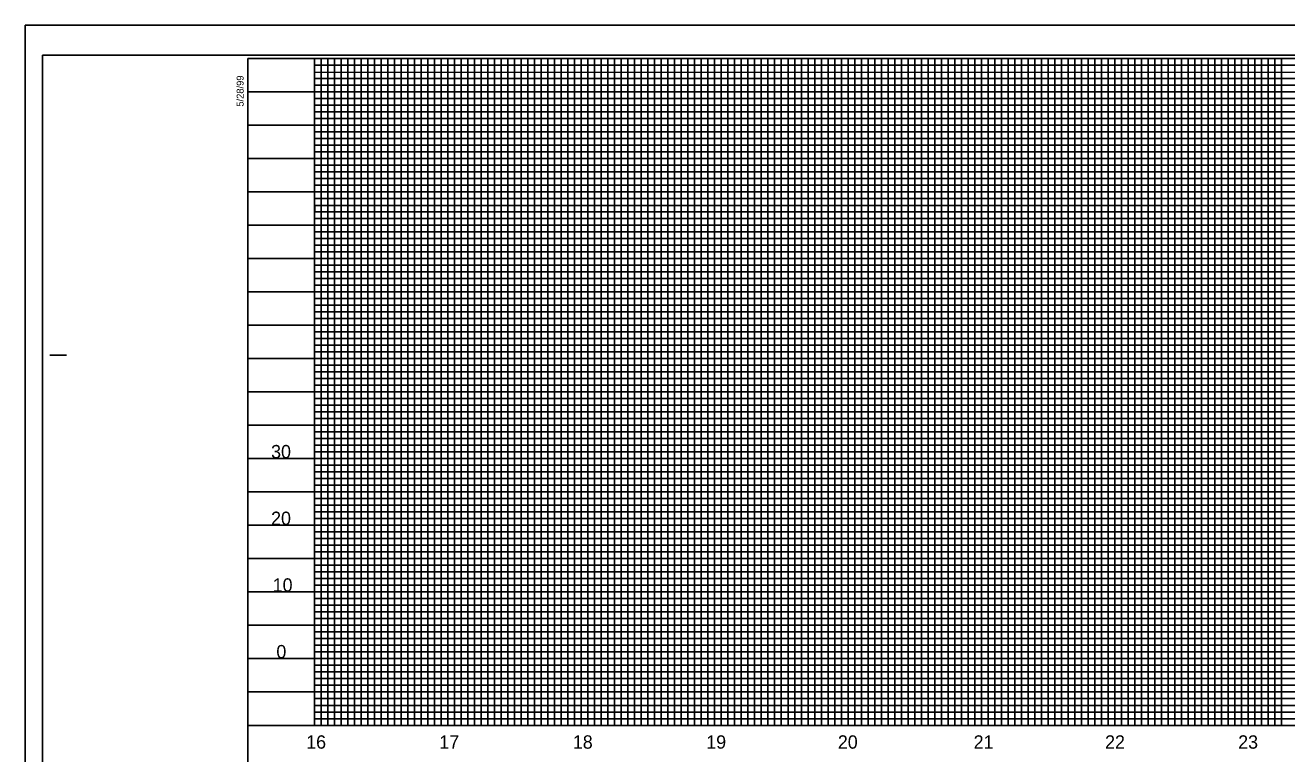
# Model space of a CAD drawing. Extents: x 2180324 to 2182216, y 74532 to 75632.
# Drawn here: x 2180324 to 2181270, y 75086 to 75632 of the extents above; entities that cross this region are included whole.
import ezdxf

# ---------------------------------------------------------------- set-up
doc = ezdxf.new("R2010")
doc.units = 0
for name, color, linetype in [('Old_Level_1', 7, 'Continuous'), ('Old_Level_11', 7, 'Continuous'), ('Old_Level_2', 7, 'Continuous'), ('Old_Level_3', 7, 'Continuous'), ('Scratch_Level_0', 7, 'Continuous'), ('Sheet Cutting Line CELL', 7, 'Continuous'), ('Sheet Plot Border Inside CELL', 7, 'Continuous'), ('Sheet Plot Border Outside CELL', 7, 'Continuous'), ('Sheet Sticker Exception Certification CELL', 7, 'Continuous'), ('Sheet Sticker Incomplete CELL', 7, 'Continuous'), ('Sheet Sticker Preliminary CELL', 7, 'Continuous')]:
    doc.layers.add(name, color=color, linetype=linetype)

msp = doc.modelspace()

# ---------------------------------------------------------------- linework, layer by layer
at = {"layer": 'Old_Level_11'}
for p, q in [((2180540.9, 75107.28), (2180540.9, 75607.28)), ((2180590.9, 75107.28), (2180590.9, 75607.28)), ((2180640.9, 75107.28), (2180640.9, 75607.28)), ((2180690.9, 75107.28), (2180690.9, 75607.28)), ((2180740.9, 75107.28), (2180740.9, 75607.28)), ((2180790.9, 75107.28), (2180790.9, 75607.28)), ((2180840.9, 75107.28), (2180840.9, 75607.28)), ((2180890.9, 75107.28), (2180890.9, 75607.28)), ((2180940.9, 75107.28), (2180940.9, 75607.28)), ((2180990.9, 75107.28), (2180990.9, 75607.28)), ((2181040.9, 75107.28), (2181040.9, 75607.28)), ((2181090.9, 75107.28), (2181090.9, 75607.28)), ((2181140.9, 75107.28), (2181140.9, 75607.28)), ((2181190.9, 75107.28), (2181190.9, 75607.28)), ((2181240.9, 75107.28), (2181240.9, 75607.28)), ((2181790.85, 75557.28), (2180490.9, 75557.28)), ((2181790.85, 75507.28), (2180490.9, 75507.28)), ((2181790.9, 75457.28), (2180490.9, 75457.28)), ((2181990.9, 75407.28), (2180490.9, 75407.28)), ((2181990.9, 75357.28), (2180490.9, 75357.28)), ((2181990.9, 75307.28), (2180490.9, 75307.28)), ((2181990.9, 75257.28), (2180490.9, 75257.28)), ((2181990.9, 75207.28), (2180490.9, 75207.28)), ((2181990.9, 75157.28), (2180490.9, 75157.28))]:
    msp.add_line(p, q, dxfattribs=at)
at = {"layer": 'Old_Level_2'}
msp.add_line((2180490.9, 75582.28), (2181790.85, 75582.28), dxfattribs=at)
for points in [[(2180565.9, 75607.28), (2180565.9, 75107.28), (2180615.9, 75107.28), (2180615.9, 75607.28), (2180665.9, 75607.28), (2180665.9, 75107.28), (2180715.9, 75107.28), (2180715.9, 75607.28), (2180765.9, 75607.28), (2180765.9, 75107.28), (2180815.9, 75107.28), (2180815.9, 75607.28), (2180865.9, 75607.28), (2180865.9, 75107.28), (2180915.9, 75107.28), (2180915.9, 75607.28), (2180965.9, 75607.28), (2180965.9, 75107.28), (2181015.9, 75107.28), (2181015.9, 75607.28), (2181065.9, 75607.28), (2181065.9, 75107.28), (2181115.9, 75107.28), (2181115.9, 75107.28), (2181115.9, 75607.28), (2181165.9, 75607.28), (2181165.9, 75107.28), (2181215.9, 75107.28), (2181215.9, 75607.28), (2181265.9, 75607.28), (2181265.9, 75107.28), (2181315.9, 75107.28)], [(2181790.9, 75532.28), (2180490.9, 75532.28), (2180490.9, 75482.28), (2181790.9, 75482.28)], [(2181990.9, 75432.28), (2180490.9, 75432.28), (2180490.9, 75382.28), (2181815.9, 75382.28)], [(2181990.9, 75332.28), (2180490.9, 75332.28), (2180490.9, 75282.28), (2181990.9, 75282.28)], [(2181990.9, 75232.28), (2180490.9, 75232.28), (2180490.9, 75182.28), (2181990.9, 75182.28)], [(2181990.9, 75132.28), (2180490.9, 75132.28)]]:
    msp.add_lwpolyline(points, dxfattribs=at)
at = {"layer": 'Scratch_Level_0'}
for p, q in [((2182007.9, 75632.28), (2180323.9, 75632.28)), ((2180323.9, 75632.28), (2180323.9, 74532.28))]:
    msp.add_line(p, q, dxfattribs=at)
at = {"layer": 'Sheet Cutting Line CELL'}
for p, q in [((2180342.4, 75384.78), (2180354.9, 75384.78)), ((2180490.9, 75107.28), (2181990.9, 75107.28))]:
    msp.add_line(p, q, dxfattribs=at)
msp.add_lwpolyline([(2181990.9, 75607.28), (2180490.9, 75607.28), (2180490.9, 74557.28), (2181990.9, 74557.28)], close=True, dxfattribs=at)
at = {"layer": 'Sheet Plot Border Inside CELL'}
msp.add_lwpolyline([(2180540.9, 75446.23), (2180540.9, 75107.28), (2181940.9, 75107.28), (2181940.9, 75446.23)], dxfattribs=at)
at = {"layer": 'Sheet Plot Border Outside CELL'}
for p, q in [((2180540.9, 75602.28), (2181790.9, 75602.28)), ((2180540.9, 75597.28), (2180540.9, 75597.28)), ((2181790.9, 75597.28), (2180540.9, 75596.93)), ((2180540.9, 75592.28), (2181790.9, 75592.28)), ((2181790.85, 75472.28), (2180540.9, 75472.28)), ((2181790.9, 75467.28), (2180540.9, 75467.28)), ((2181790.9, 75462.28), (2180540.9, 75462.28)), ((2180540.9, 75452.28), (2181790.9, 75452.28)), ((2181790.9, 75447.28), (2180540.9, 75447.28)), ((2180540.9, 75442.28), (2181940.9, 75442.28)), ((2181940.9, 75422.28), (2180540.9, 75422.28)), ((2180540.9, 75417.28), (2181940.9, 75417.28)), ((2181940.9, 75397.28), (2180540.9, 75397.28)), ((2180540.9, 75392.28), (2181940.9, 75392.28)), ((2181940.9, 75372.28), (2180540.9, 75372.28)), ((2180540.9, 75367.28), (2181940.9, 75367.28)), ((2181940.9, 75362.28), (2180540.9, 75362.28)), ((2180540.9, 75352.28), (2181940.9, 75352.28)), ((2181940.9, 75347.28), (2180540.9, 75347.28)), ((2180540.9, 75342.28), (2181940.9, 75342.28)), ((2181940.9, 75337.28), (2180540.9, 75337.28)), ((2180540.9, 75327.28), (2181940.9, 75327.28)), ((2181940.9, 75322.28), (2180540.9, 75322.28)), ((2180540.9, 75317.28), (2181940.9, 75317.28)), ((2181940.9, 75312.28), (2180540.9, 75312.28)), ((2180540.9, 75302.28), (2181940.9, 75302.28)), ((2181940.9, 75297.28), (2180540.9, 75297.28)), ((2180540.9, 75292.28), (2181940.9, 75292.28)), ((2181940.9, 75287.28), (2180540.9, 75287.28)), ((2180540.9, 75277.28), (2181940.9, 75277.28)), ((2181940.9, 75272.28), (2180540.9, 75272.28)), ((2180540.9, 75267.28), (2181940.9, 75267.28)), ((2181940.9, 75262.28), (2180540.9, 75262.28)), ((2180540.9, 75252.28), (2181940.9, 75252.28)), ((2181940.9, 75247.28), (2180540.9, 75247.28)), ((2180540.9, 75242.28), (2181940.9, 75242.28)), ((2181940.9, 75237.28), (2180540.9, 75237.28)), ((2180540.9, 75227.28), (2181940.9, 75227.28)), ((2181940.9, 75222.28), (2180540.9, 75222.28)), ((2181940.9, 75217.28), (2180540.9, 75217.28)), ((2181940.9, 75212.28), (2180540.9, 75212.28)), ((2180540.9, 75202.28), (2181940.9, 75202.28)), ((2181940.9, 75197.28), (2180540.9, 75197.28)), ((2180540.9, 75192.28), (2181940.9, 75192.28)), ((2181940.9, 75187.28), (2180540.9, 75187.28)), ((2180540.9, 75177.28), (2181940.9, 75177.28)), ((2181940.9, 75172.28), (2180540.9, 75172.28)), ((2180540.9, 75167.28), (2181940.9, 75167.28)), ((2181940.9, 75162.28), (2180540.9, 75162.28)), ((2180540.9, 75152.28), (2181940.9, 75152.28)), ((2181940.9, 75147.28), (2180540.9, 75147.28)), ((2180540.9, 75142.28), (2181940.9, 75142.28)), ((2181940.9, 75137.28), (2180540.9, 75137.28)), ((2180540.9, 75127.28), (2181940.9, 75127.28)), ((2181940.9, 75122.28), (2180540.9, 75122.28)), ((2180540.9, 75117.28), (2181940.9, 75117.28))]:
    msp.add_line(p, q, dxfattribs=at)
for points in [[(2180545.9, 75607.28), (2180545.9, 75107.28), (2180550.9, 75107.28), (2180550.9, 75607.28), (2180555.9, 75607.28), (2180555.9, 75107.28), (2180560.9, 75107.28), (2180560.9, 75607.28), (2180570.9, 75607.28), (2180570.9, 75107.28), (2180575.9, 75107.28), (2180575.9, 75607.28), (2180580.9, 75607.28), (2180580.9, 75107.28), (2180585.9, 75107.28), (2180595.9, 75107.28), (2180600.9, 75107.28), (2180600.9, 75607.28), (2180605.9, 75607.28), (2180605.9, 75107.28), (2180610.9, 75107.28), (2180610.9, 75607.28), (2180620.9, 75607.28), (2180620.9, 75107.28), (2180625.9, 75107.28), (2180625.9, 75607.28), (2180630.9, 75607.28), (2180630.9, 75107.28), (2180635.9, 75107.28), (2180635.9, 75607.28), (2180645.9, 75607.28), (2180645.9, 75107.28), (2180650.9, 75107.28), (2180650.9, 75607.28), (2180655.9, 75607.28), (2180655.9, 75107.28), (2180660.9, 75107.28), (2180660.9, 75607.28), (2180670.9, 75607.28), (2180670.9, 75107.28), (2180675.9, 75107.28), (2180675.9, 75607.28), (2180680.9, 75607.28), (2180680.9, 75107.28), (2180685.9, 75107.28), (2180685.9, 75607.28), (2180695.9, 75607.28), (2180695.9, 75107.28), (2180700.9, 75107.28), (2180700.9, 75607.28), (2180705.9, 75607.28), (2180705.9, 75107.28), (2180710.9, 75107.28), (2180710.9, 75607.28), (2180720.9, 75607.28), (2180720.9, 75107.28), (2180725.9, 75107.28), (2180725.9, 75607.28), (2180730.9, 75607.28), (2180730.9, 75107.28), (2180735.9, 75107.28), (2180735.9, 75607.28), (2180745.9, 75607.28), (2180745.9, 75107.28), (2180750.9, 75107.28), (2180750.9, 75607.28), (2180755.9, 75607.28), (2180755.9, 75107.28)], [(2180585.9, 75107.28), (2180585.9, 75607.28), (2180595.9, 75607.28), (2180595.9, 75107.28)], [(2180755.9, 75107.28), (2180760.9, 75107.28), (2180760.9, 75607.28), (2180770.9, 75607.28), (2180770.9, 75107.28), (2180775.9, 75107.28), (2180775.9, 75607.28), (2180780.9, 75607.28), (2180780.9, 75107.28), (2180785.9, 75107.28), (2180785.9, 75607.28), (2180795.9, 75607.28), (2180795.9, 75107.28), (2180800.9, 75107.28), (2180800.9, 75607.28), (2180805.9, 75607.28), (2180805.9, 75107.28), (2180810.9, 75107.28), (2180810.9, 75607.28), (2180820.9, 75607.28), (2180820.9, 75107.28), (2180825.9, 75107.28), (2180825.9, 75607.28), (2180830.9, 75607.28), (2180830.9, 75107.28), (2180835.9, 75107.28), (2180835.9, 75607.28), (2180845.9, 75607.28), (2180845.9, 75107.28), (2180850.9, 75107.28), (2180850.9, 75607.28), (2180855.9, 75607.28), (2180855.9, 75107.28), (2180860.9, 75107.28), (2180860.9, 75607.28), (2180870.9, 75607.28), (2180870.9, 75107.28), (2180875.9, 75107.28), (2180875.9, 75607.28), (2180880.9, 75607.28), (2180880.9, 75107.28), (2180885.9, 75107.28), (2180885.9, 75607.28), (2180895.9, 75607.28), (2180895.9, 75107.28), (2180900.9, 75107.28), (2180900.9, 75607.28), (2180905.9, 75607.28), (2180905.9, 75107.28), (2180910.9, 75107.28), (2180910.9, 75607.28), (2180920.9, 75607.28), (2180920.9, 75107.28), (2180925.9, 75107.28), (2180925.9, 75607.28), (2180930.9, 75607.28), (2180930.9, 75107.28), (2180935.9, 75107.28), (2180935.9, 75607.28), (2180945.9, 75607.28), (2180945.9, 75107.28), (2180950.9, 75107.28), (2180950.9, 75607.28), (2180955.9, 75607.28), (2180955.9, 75107.28), (2180960.9, 75107.28), (2180960.9, 75607.28), (2180970.9, 75607.28), (2180970.9, 75107.28), (2180975.9, 75107.28), (2180975.9, 75607.28), (2180980.9, 75607.28), (2180980.9, 75107.28), (2180985.9, 75107.28), (2180985.9, 75607.28), (2180995.9, 75607.28), (2180995.9, 75107.28), (2181000.9, 75107.28), (2181000.9, 75607.28), (2181005.9, 75607.28), (2181005.9, 75107.28), (2181010.9, 75107.28), (2181010.9, 75607.28), (2181020.9, 75607.28), (2181020.9, 75107.28), (2181025.9, 75107.28), (2181025.9, 75607.28), (2181030.9, 75607.28), (2181030.9, 75107.28), (2181035.9, 75107.28), (2181035.9, 75607.28), (2181045.9, 75607.28), (2181045.9, 75107.28), (2181050.9, 75107.28), (2181050.9, 75607.28), (2181055.9, 75607.28), (2181055.9, 75107.28), (2181060.9, 75107.28), (2181060.9, 75607.28), (2181070.9, 75607.28)], [(2181070.9, 75607.28), (2181070.9, 75107.28), (2181075.9, 75107.28), (2181075.9, 75607.28), (2181080.9, 75607.28), (2181080.9, 75107.28), (2181085.9, 75107.28), (2181085.9, 75607.28), (2181095.9, 75607.28), (2181095.9, 75107.28), (2181100.9, 75107.28), (2181100.9, 75607.28), (2181105.9, 75607.28), (2181105.9, 75107.28), (2181110.9, 75107.28), (2181110.9, 75607.28), (2181120.9, 75607.28), (2181120.9, 75107.28), (2181125.9, 75107.28), (2181125.9, 75607.28), (2181130.9, 75607.28), (2181130.9, 75107.28), (2181135.9, 75107.28), (2181135.9, 75607.28), (2181145.9, 75607.28), (2181145.9, 75107.28), (2181150.9, 75107.28), (2181150.9, 75607.28), (2181155.9, 75607.28), (2181155.9, 75107.28), (2181160.9, 75107.28), (2181160.9, 75607.28), (2181170.9, 75607.28), (2181170.9, 75107.28), (2181175.9, 75107.28), (2181175.9, 75607.28), (2181180.9, 75607.28), (2181180.9, 75107.28), (2181185.9, 75107.28), (2181185.9, 75607.28), (2181195.9, 75607.28), (2181195.9, 75107.28), (2181195.9, 75107.28), (2181200.9, 75107.28), (2181200.9, 75607.28), (2181205.9, 75607.28), (2181205.9, 75107.28), (2181210.9, 75107.28), (2181210.9, 75607.28), (2181220.9, 75607.28), (2181220.9, 75107.28), (2181225.9, 75107.28), (2181225.9, 75607.28), (2181230.9, 75607.28), (2181230.9, 75107.28), (2181235.9, 75107.28), (2181235.9, 75607.28), (2181245.9, 75607.28), (2181245.9, 75107.28), (2181250.9, 75107.28), (2181250.9, 75607.28), (2181255.9, 75607.28), (2181255.9, 75107.28), (2181260.9, 75107.28), (2181260.9, 75607.28), (2181270.9, 75607.28)], [(2181790.9, 75587.28), (2180540.9, 75587.28), (2180540.9, 75577.28), (2181790.9, 75577.28)], [(2181790.85, 75572.28), (2180540.9, 75572.28), (2180540.9, 75567.28), (2181790.9, 75567.28)], [(2181790.9, 75562.28), (2180540.9, 75562.28), (2180540.9, 75552.28), (2181790.9, 75552.28)], [(2181790.9, 75547.28), (2180540.9, 75547.28), (2180540.9, 75542.28), (2181790.9, 75542.28)], [(2181790.9, 75537.28), (2180540.9, 75537.28), (2180540.9, 75527.28), (2181790.9, 75527.28)], [(2181790.9, 75522.28), (2180540.9, 75522.28), (2180540.9, 75517.28), (2181790.9, 75517.28)], [(2181790.9, 75512.28), (2180540.9, 75512.28), (2180540.9, 75502.28), (2181790.9, 75502.28)], [(2181790.9, 75497.18), (2180541, 75497.18), (2180541, 75492.28), (2181790.9, 75492.28)], [(2181790.9, 75487.28), (2180540.9, 75487.28), (2180540.9, 75477.28), (2181790.9, 75477.28)], [(2181940.9, 75437.28), (2180540.9, 75437.28), (2180540.9, 75427.28), (2181940.9, 75427.28)], [(2181940.9, 75412.28), (2180540.9, 75412.28), (2180540.9, 75402.28), (2181940.9, 75402.28)], [(2181940.9, 75387.28), (2180540.9, 75387.28), (2180540.9, 75377.28), (2181940.9, 75377.28)], [(2181940.9, 75112.28), (2180540.9, 75112.28)]]:
    msp.add_lwpolyline(points, dxfattribs=at)
at = {"layer": 'Sheet Sticker Exception Certification CELL'}
for points in [[(2180540.9, 75607.28), (2180540.9, 75107.28), (2180590.9, 75107.28), (2180590.9, 75607.28), (2180640.9, 75607.28), (2180640.9, 75107.28), (2180690.9, 75107.28), (2180690.9, 75607.28), (2180740.9, 75607.28), (2180740.9, 75107.28), (2180790.9, 75107.28), (2180790.9, 75607.28), (2180840.9, 75607.28), (2180840.9, 75107.28), (2180890.9, 75107.28), (2180890.9, 75607.28), (2180940.9, 75607.28), (2180940.9, 75107.28), (2180990.9, 75107.28), (2180990.9, 75607.28), (2181040.9, 75607.28), (2181040.9, 75107.28), (2181090.9, 75107.28), (2181090.9, 75607.28), (2181140.9, 75607.28), (2181140.9, 75107.28), (2181190.9, 75107.28), (2181190.9, 75607.28), (2181240.9, 75607.28), (2181240.9, 75107.28), (2181290.9, 75107.28)], [(2180490.9, 75557.28), (2181790.9, 75557.28)], [(2181790.9, 75507.28), (2180490.9, 75507.28), (2180490.9, 75457.28), (2181790.9, 75457.28)], [(2181990.9, 75407.28), (2180490.9, 75407.28), (2180490.9, 75357.28), (2181990.9, 75357.28)], [(2181990.9, 75307.28), (2180490.9, 75307.28), (2180490.9, 75257.28), (2181990.9, 75257.28)], [(2181990.9, 75207.28), (2180490.9, 75207.28), (2180490.9, 75207.28), (2180490.9, 75157.28), (2181990.9, 75157.28)]]:
    msp.add_lwpolyline(points, dxfattribs=at)
at = {"layer": 'Sheet Sticker Incomplete CELL'}
msp.add_lwpolyline([(2180323.9, 74532.28), (2182007.9, 74532.28), (2182007.9, 75632.28), (2180323.9, 75632.28)], close=True, dxfattribs=at)
at = {"layer": 'Sheet Sticker Preliminary CELL'}
msp.add_lwpolyline([(2180336.9, 74554.73), (2182003.4, 74554.73), (2182003.4, 75609.83), (2180336.9, 75609.83)], close=True, dxfattribs=at)

# ---------------------------------------------------------------- texts
at = {"layer": 'Old_Level_1'}
for s, p in [('16', (2180534.59, 75089.78)), ('17', (2180634.44, 75089.78)), ('18', (2180734.57, 75089.78)), ('19', (2180834.61, 75089.78)), ('20', (2180933.29, 75089.78)), ('21', (2181035.13, 75089.78)), ('22', (2181133.68, 75089.78)), ('23', (2181233.51, 75089.78))]:
    msp.add_text(s, height=10, dxfattribs=at).set_placement(p)
at = {"layer": 'Old_Level_3'}
for s, p in [('30', (2180508.29, 75307.53)), ('20', (2180508.29, 75257.53)), ('10', (2180509.49, 75207.53)), ('0', (2180512.24, 75157.53))]:
    msp.add_text(s, height=10, dxfattribs=at).set_placement(p)
at = {"layer": 'Sheet Cutting Line CELL'}
msp.add_text('5/28/99', height=5.25, rotation=90, dxfattribs=at).set_placement((2180487.67, 75571.19))

doc.saveas('drawing.dxf')
